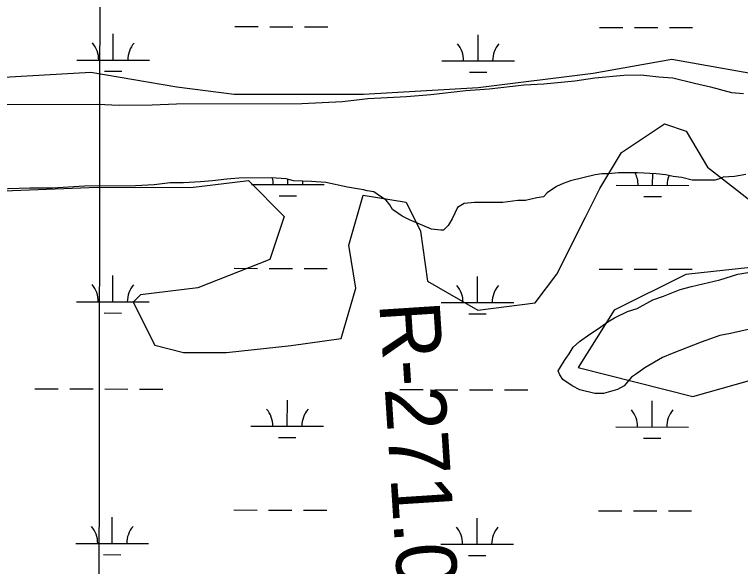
# Model space of a CAD drawing. Extents: x 3219052 to 3256913, y 800770 to 826146.
# Drawn here: x 3228359 to 3229358, y 818838 to 819598 of the extents above; entities that cross this region are included whole.
import ezdxf

# ---------------------------------------------------------------- set-up
doc = ezdxf.new("R2010")
doc.units = 0
for name, color, linetype in [('V-GRID-MAJR', 7, 'Continuous'), ('V-RIVR-RANG-IDEN', 7, 'Continuous'), ('V-SITE-VEGE', 7, 'Continuous'), ('V-TOPO-SHOR', 7, 'Continuous'), ('V-WETL-SWMP', 7, 'Continuous')]:
    doc.layers.add(name, color=color, linetype=linetype)

msp = doc.modelspace()

# ---------------------------------------------------------------- linework, layer by layer
at = {"layer": 'V-GRID-MAJR'}
msp.add_spline([(3228457.14, 806177.393), (3228465.955, 812237.661), (3228474.772, 818299.872), (3228483.589, 824362.121), (3228483.592, 824364.024)], degree=3, dxfattribs=at)
at = {"layer": 'V-SITE-VEGE'}
for p, q in [((3229157.156, 819510.517), (3229197.319, 819514.5430000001)), ((3229197.319, 819514.5429999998), (3229220.648, 819514.6229999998)), ((3229220.648, 819514.623), (3229245.281, 819512.116)), ((3229087.196, 819502.501), (3229129.95, 819506.536)), ((3229129.95, 819506.536), (3229157.156, 819510.517)), ((3229245.281, 819512.1159999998), (3229264.725, 819510.886)), ((3229264.725, 819510.886), (3229294.56, 819503.214)), ((3229294.56, 819503.214), (3229316.611, 819498.104)), ((3228931.724, 819487.71), (3228979.66, 819493.06)), ((3228979.66, 819493.06), (3229012.051, 819495.763)), ((3229012.051, 819495.763), (3229059.984, 819501.111)), ((3229059.984, 819501.111), (3229087.196, 819502.501)), ((3229316.611, 819498.104), (3229345.15, 819490.4280000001)), ((3228844.9080000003, 819482.228), (3228898.039, 819485.003)), ((3228898.039, 819485.0029999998), (3228931.724, 819487.71)), ((3229345.15, 819490.4279999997), (3229362.003, 819489.1869999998)), ((3228259.128, 819473.737), (3228472.972, 819474.47)), ((3228472.972, 819474.4699999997), (3228502.785, 819473.2779999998)), ((3228502.785, 819473.2779999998), (3228548.146, 819473.4339999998)), ((3228548.146, 819473.4339999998), (3228581.838, 819474.8449999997)), ((3228581.838, 819474.845), (3228754.21, 819475.437)), ((3228754.21, 819475.4369999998), (3228809.93, 819478.22)), ((3228809.93, 819478.22), (3228844.9080000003, 819482.228)), ((3228711.792, 819372.9059999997), (3228667.727, 819372.7519999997)), ((3228732.532, 819371.6829999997), (3228711.792, 819372.9059999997)), ((3229157.615, 819377.0259999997), (3229123.943, 819369.1349999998)), ((3229166.681, 819378.353), (3229157.615, 819377.0260000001)), ((3229175.754, 819378.384), (3229166.681, 819378.353)), ((3229190.006, 819379.73), (3229175.754, 819378.384)), ((3229215.923, 819379.8200000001), (3229190.006, 819379.73)), ((3229241.8510000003, 819378.611), (3229215.923, 819379.8200000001)), ((3229254.815, 819377.36), (3229241.8510000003, 819378.611)), ((3229265.194, 819374.8039999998), (3229254.815, 819377.3599999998)), ((3229276.861, 819373.549), (3229265.194, 819374.8039999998)), ((3229291.134, 819369.7089999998), (3229276.861, 819373.549)), ((3229333.886, 819373.7429999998), (3229327.414, 819371.1299999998)), ((3229349.434, 819375.0929999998), (3229333.886, 819373.7429999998)), ((3229364.977, 819377.7390000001), (3229349.434, 819375.0929999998)), ((3228551.116, 819363.2799999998), (3228525.2, 819361.8960000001)), ((3228573.14, 819365.949), (3228551.116, 819363.2799999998)), ((3228591.2830000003, 819366.01), (3228573.14, 819365.949)), ((3228614.608, 819367.3879999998), (3228591.2830000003, 819366.01)), ((3228631.451, 819368.7399999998), (3228614.608, 819367.3879999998)), ((3228650.882, 819371.398), (3228631.451, 819368.7399999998)), ((3228667.727, 819372.7519999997), (3228650.882, 819371.398)), ((3228742.909, 819369.123), (3228732.532, 819371.6829999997)), ((3228767.538, 819367.9130000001), (3228742.909, 819369.123)), ((3228786.984, 819366.6819999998), (3228767.538, 819367.9129999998)), ((3228816.813, 819360.3039999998), (3228786.984, 819366.6819999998)), ((3229113.589, 819365.211), (3229104.5300000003, 819361.2919999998)), ((3229123.943, 819369.135), (3229113.589, 819365.211)), ((3229322.237, 819369.8149999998), (3229291.134, 819369.7089999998)), ((3229327.414, 819371.13), (3229322.237, 819369.8150000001)), ((3228380.052, 819358.805), (3228332.107, 819357.345)), ((3228411.16, 819358.912), (3228380.052, 819358.805)), ((3228455.214, 819361.654), (3228411.16, 819358.912)), ((3228525.2, 819361.8960000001), (3228455.214, 819361.654)), ((3228838.86, 819356.491), (3228816.813, 819360.304)), ((3228844.0470000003, 819355.2129999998), (3228838.86, 819356.4909999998)), ((3228853.124, 819353.9489999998), (3228844.0470000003, 819355.2129999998)), ((3228862.219, 819347.4999999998), (3228853.124, 819353.9489999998)), ((3229104.5300000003, 819361.2919999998), (3229091.6010000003, 819352.176)), ((3228870.014, 819342.3429999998), (3228862.219, 819347.4999999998)), ((3229077.3680000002, 819345.6489999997), (3229061.828, 819341.7039999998)), ((3229086.434, 819346.974), (3229077.3680000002, 819345.649)), ((3229091.6010000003, 819352.176), (3229086.434, 819346.974)), ((3228875.22, 819335.8799999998), (3228870.014, 819342.3429999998)), ((3228879.13, 819329.414), (3228875.22, 819335.8799999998)), ((3228977.597, 819337.529), (3228968.545, 819332.312)), ((3228991.852, 819338.872), (3228977.597, 819337.529)), ((3229030.733, 819339.005), (3228991.852, 819338.872)), ((3229051.461, 819341.67), (3229030.733, 819339.005)), ((3229061.828, 819341.704), (3229051.461, 819341.67)), ((3228892.12, 819320.3869999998), (3228879.13, 819329.414)), ((3228968.545, 819332.312), (3228960.822, 819316.733)), ((3228902.508, 819315.2359999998), (3228892.12, 819320.3869999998)), ((3228920.677, 819307.523), (3228902.508, 819315.2359999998)), ((3228960.822, 819316.733), (3228955.669, 819307.6439999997)), ((3228932.359, 819302.3809999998), (3228920.677, 819307.523)), ((3228955.669, 819307.6439999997), (3228949.2120000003, 819301.142)), ((3228945.323, 819301.127), (3228932.359, 819302.3809999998)), ((3228949.2120000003, 819301.142), (3228945.323, 819301.127)), ((3229353.786, 819240.3200000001), (3229370.625, 819242.97)), ((3229329.188, 819232.4599999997), (3229353.786, 819240.3200000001)), ((3229274.799, 819219.314), (3229290.3370000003, 819223.2540000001)), ((3229290.3370000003, 819223.2540000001), (3229329.188, 819232.46)), ((3229251.499, 819210.1589999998), (3229274.799, 819219.314)), ((3229215.272, 819193.188), (3229237.2630000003, 819204.9269999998)), ((3229237.2630000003, 819204.9269999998), (3229251.499, 819210.1589999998)), ((3229202.324, 819189.2549999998), (3229215.272, 819193.188)), ((3229184.2120000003, 819180.121), (3229202.324, 819189.255)), ((3229162.227, 819165.789), (3229175.156, 819174.905)), ((3229175.156, 819174.905), (3229184.2120000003, 819180.121)), ((3229150.59, 819157.9719999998), (3229162.227, 819165.789)), ((3229372.188, 819165.2139999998), (3229343.698, 819158.636)), ((3229136.369, 819147.5539999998), (3229150.59, 819157.9719999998)), ((3229329.45, 819155.9940000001), (3229303.559, 819146.835)), ((3229343.698, 819158.636), (3229329.45, 819155.9940000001)), ((3229127.325, 819139.747), (3229136.369, 819147.5539999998)), ((3229303.559, 819146.835), (3229263.437, 819131.143)), ((3229122.1720000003, 819130.6579999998), (3229127.325, 819139.747)), ((3229115.723, 819121.5650000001), (3229122.1720000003, 819130.6579999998)), ((3229250.4930000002, 819125.915), (3229225.919, 819111.5749999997)), ((3229263.437, 819131.143), (3229250.4930000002, 819125.915)), ((3229109.278, 819111.1730000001), (3229115.723, 819121.5650000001)), ((3229106.697, 819107.2760000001), (3229109.278, 819111.1730000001)), ((3229109.308, 819102.1009999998), (3229106.697, 819107.2760000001)), ((3229225.919, 819111.5749999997), (3229212.99, 819102.4569999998)), ((3229113.218, 819095.635), (3229109.308, 819102.1009999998)), ((3229126.211, 819086.6079999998), (3229113.218, 819095.635)), ((3229207.819, 819098.552), (3229197.491, 819086.851)), ((3229212.99, 819102.4569999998), (3229207.819, 819098.552)), ((3229136.596, 819081.4589999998), (3229126.211, 819086.6079999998)), ((3229197.491, 819086.851), (3229188.437, 819081.635)), ((3229157.35, 819076.345), (3229136.596, 819081.459)), ((3229169.014, 819076.386), (3229157.35, 819076.345)), ((3229188.437, 819081.635), (3229169.014, 819076.386))]:
    msp.add_line(p, q, dxfattribs=at)
at = {"layer": 'V-TOPO-SHOR'}
for points in [[(3229431.101306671, 819506.0393770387), (3229263.365659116, 819536.0024266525), (3229154.749294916, 819516.4890830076), (3228996.780662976, 819497.0791772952), (3228838.8327186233, 819487.5397251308), (3228790.3889561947, 819487.6412589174)], [(3228790.3889561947, 819487.6412589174), (3228661.164554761, 819487.9121016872), (3228582.221613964, 819497.9480559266), (3228463.8175465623, 819517.9372140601), (3228295.9991486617, 819508.418449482), (3228138.0512043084, 819498.8789973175), (3227970.232806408, 819489.3602327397), (3227832.025769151, 819479.7794054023), (3227703.709873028, 819480.0483440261)], [(3228226.574972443, 819350.6360058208), (3228473.3569987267, 819359.989269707), (3228601.67289485, 819359.720331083), (3228680.6572108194, 819369.4252839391), (3228729.9060406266, 819319.9695782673), (3228710.041008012, 819260.7882321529), (3228611.253722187, 819221.5132938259), (3228532.2694062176, 819211.8083409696), (3228522.378265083, 819201.9585750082), (3228551.865500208, 819142.6737909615), (3228591.326626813, 819132.7205870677), (3228650.5493481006, 819132.5964615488), (3228739.404117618, 819142.2807268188), (3228808.51798004, 819152.0063672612), (3228828.4037002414, 819221.0581669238), (3228818.6573722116, 819280.3015757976), (3228838.543092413, 819349.3533754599), (3228897.7451261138, 819339.3587963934), (3228917.4032828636, 819299.8356070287), (3228927.1289233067, 819230.721744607), (3228996.139347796, 819191.0951173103), (3229075.123663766, 819200.8000701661), (3229104.8177747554, 819240.2198215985), (3229144.4650896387, 819319.100699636), (3229164.2887470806, 819358.5411386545), (3229194.0035456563, 819407.8313436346), (3229253.3090172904, 819447.1890323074), (3229282.899690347, 819437.2565160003), (3229312.407613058, 819387.8421855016), (3229401.096881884, 819318.5628223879)], [(3229371.340708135, 819249.5317103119), (3229282.485938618, 819239.8474450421), (3229183.677965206, 819190.7020531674), (3229134.160196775, 819111.8418627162), (3229292.0047031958, 819072.0290471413), (3229430.273803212, 819111.2212351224)]]:
    msp.add_lwpolyline(points, dxfattribs=at)
at = {"layer": 'V-WETL-SWMP'}
for p, q in [((3228661.935138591, 819581.1993197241), (3228693.9350682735, 819581.1322507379)), ((3228709.9350331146, 819581.0987162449), (3228741.934962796, 819581.0316472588)), ((3228757.934927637, 819580.9981127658), (3228789.93485732, 819580.9310437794)), ((3229163.842035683, 819580.1473678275), (3229195.8419653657, 819580.0802988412)), ((3229211.8419302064, 819580.0467643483), (3229243.8418598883, 819579.9796953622)), ((3229259.841824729, 819579.9461608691), (3229291.841754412, 819579.8790918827)), ((3228494.7741956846, 819535.1196136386), (3228494.8496460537, 819571.1195023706)), ((3228996.6810927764, 819534.067661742), (3228996.7565431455, 819570.067550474)), ((3228444.7743055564, 819535.2244089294), (3228544.7740858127, 819535.0148183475)), ((3228946.681202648, 819534.1724570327), (3229046.6809829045, 819533.9628664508)), ((3228482.741881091, 819519.7138122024), (3228506.7418283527, 819519.663510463)), ((3228984.648778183, 819518.6618603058), (3229008.6487254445, 819518.6115585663)), ((3229157.155977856, 819510.5163820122), (3229197.318977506, 819514.5423722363)), ((3229197.318977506, 819514.5423722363), (3229220.646977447, 819514.6223705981)), ((3229220.646977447, 819514.6223705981), (3229245.280977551, 819512.1153735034)), ((3229087.1969785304, 819502.5004008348), (3229129.9529781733, 819506.535390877)), ((3229129.9529781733, 819506.5353908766), (3229157.155977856, 819510.5163820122)), ((3229245.280977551, 819512.1153735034), (3229264.7249775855, 819510.8853744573)), ((3229264.7249775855, 819510.8853744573), (3229294.5609780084, 819503.2123862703)), ((3229294.5609780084, 819503.2123862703), (3229316.6109782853, 819498.1033939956)), ((3228931.7239798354, 819487.7104372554), (3228979.6589793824, 819493.0584246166)), ((3228979.6589793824, 819493.0584246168), (3229012.0499791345, 819495.7624177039)), ((3229012.0499791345, 819495.7624177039), (3229059.984978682, 819501.1104050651)), ((3229059.984978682, 819501.1104050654), (3229087.1969785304, 819502.5004008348)), ((3229316.6109782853, 819498.1033939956), (3229345.149978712, 819490.4254059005)), ((3228844.907980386, 819482.2274526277), (3228898.0359800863, 819485.0024442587)), ((3228898.0359800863, 819485.0024442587), (3228931.7239798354, 819487.7104372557)), ((3229345.149978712, 819490.4254059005), (3229362.002978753, 819489.1874070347)), ((3228259.128982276, 819473.7365053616), (3228472.9719817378, 819474.4704903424)), ((3228472.9719817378, 819474.4704903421), (3228502.7849817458, 819473.2774905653)), ((3228502.7849817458, 819473.2774905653), (3228548.1459816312, 819473.4324873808)), ((3228548.1459816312, 819473.4324873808), (3228581.8379814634, 819474.8444826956)), ((3228581.8379814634, 819474.8444826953), (3228754.2089810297, 819475.4364705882)), ((3228754.2089810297, 819475.4364705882), (3228809.9289807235, 819478.2194620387)), ((3228809.9289807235, 819478.2194620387), (3228844.907980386, 819482.2274526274)), ((3228711.7909876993, 819372.9036567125), (3228667.7269878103, 819372.7526598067)), ((3228732.53198773, 819371.6796575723), (3228711.7909876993, 819372.9036567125)), ((3229157.613986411, 819377.0266207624), (3229123.9439869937, 819369.1346370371)), ((3229166.6819863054, 819378.3536178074), (3229157.613986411, 819377.0266207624)), ((3229175.7539862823, 819378.3846171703), (3229166.6819863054, 819378.3536178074)), ((3229190.004986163, 819379.7296138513), (3229175.7539862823, 819378.3846171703)), ((3229215.925986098, 819379.8186120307), (3229190.004986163, 819379.7296138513)), ((3229241.850986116, 819378.6116125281), (3229215.925986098, 819379.8186120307)), ((3229236.794567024, 819362.7511830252), (3229236.8282982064, 819378.8454556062)), ((3229254.814986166, 819377.3606139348), (3229241.850986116, 819378.6116125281)), ((3229265.1929863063, 819374.8036178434), (3229254.814986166, 819377.3606139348)), ((3229276.8609863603, 819373.5476193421), (3229265.1929863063, 819374.8036178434)), ((3229291.130986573, 819369.7086252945), (3229276.8609863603, 819373.5476193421)), ((3229333.885986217, 819373.7436153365), (3229327.4149863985, 819371.1296204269)), ((3229349.4339860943, 819375.0926119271), (3229333.885986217, 819373.7436153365)), ((3229364.976985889, 819377.7386061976), (3229349.4339860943, 819375.0926119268)), ((3228551.115988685, 819363.2806842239), (3228525.1999888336, 819361.8956883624)), ((3228573.1389884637, 819365.947678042), (3228551.115988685, 819363.2806842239)), ((3228591.2839884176, 819366.0096767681), (3228573.1389884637, 819365.947678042)), ((3228614.607988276, 819367.3866728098), (3228591.2839884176, 819366.0096767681)), ((3228631.4509881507, 819368.7396693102), (3228614.607988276, 819367.3866728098)), ((3228650.8829879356, 819371.3986633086), (3228631.4509881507, 819368.7396693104)), ((3228667.7269878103, 819372.7526598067), (3228650.8829879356, 819371.3986633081)), ((3228684.8877798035, 819363.9079302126), (3228784.8875600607, 819363.6983396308)), ((3228742.9089878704, 819369.1226614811), (3228732.53198773, 819371.6796575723)), ((3228734.887669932, 819363.8031349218), (3228734.9029534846, 819371.0954280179)), ((3228767.537987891, 819367.9116620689), (3228742.9089878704, 819369.1226614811)), ((3228786.9829879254, 819366.6816630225), (3228767.537987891, 819367.9116620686)), ((3228816.8139882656, 819360.3046725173), (3228786.9829879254, 819366.6816630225)), ((3229113.5889872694, 819365.2106447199), (3229104.5299875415, 819361.2916523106)), ((3229123.9439869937, 819369.1346370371), (3229113.5889872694, 819365.2106447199)), ((3229186.7946768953, 819362.8559783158), (3229286.7944571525, 819362.6463877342)), ((3229322.234986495, 819369.8156231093), (3229291.130986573, 819369.7086252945)), ((3229327.4149863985, 819371.1296204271), (3229322.234986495, 819369.8156231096)), ((3228380.0549893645, 819358.8047031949), (3228332.105989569, 819357.3447088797)), ((3228411.1589892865, 819358.9117010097), (3228380.0549893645, 819358.8047031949)), ((3228455.2149890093, 819361.6546932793), (3228411.1589892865, 819358.9117010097)), ((3228525.1999888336, 819361.8956883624), (3228455.2149890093, 819361.6546932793)), ((3228838.858988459, 819356.4916779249), (3228816.8139882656, 819360.3046725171)), ((3228844.0479885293, 819355.2136798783), (3228838.858988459, 819356.4916779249)), ((3228853.1249885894, 819353.9486815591), (3228844.0479885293, 819355.2136798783)), ((3228862.2189889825, 819347.4996925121), (3228853.1249885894, 819353.9486815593)), ((3229104.5299875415, 819361.2916523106), (3229091.600988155, 819352.1756694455)), ((3228722.8553553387, 819348.3973334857), (3228746.8553026, 819348.3470317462)), ((3228870.0129892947, 819342.342701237), (3228862.2189889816, 819347.4996925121)), ((3229077.3669886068, 819345.6466820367), (3229061.827988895, 819341.704690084)), ((3229086.4349885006, 819346.9736790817), (3229077.3669886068, 819345.6466820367)), ((3229091.600988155, 819352.1756694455), (3229086.4349885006, 819346.9736790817)), ((3229224.7622524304, 819347.3453815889), (3229248.762199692, 819347.2950798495)), ((3228875.2189896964, 819335.879712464), (3228870.0129892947, 819342.342701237)), ((3228879.1289901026, 819329.4137237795), (3228875.2189896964, 819335.879712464)), ((3228977.599989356, 819337.527702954), (3228968.545989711, 819332.3127128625)), ((3228991.851989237, 819338.8726996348), (3228977.599989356, 819337.527702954)), ((3229030.73298914, 819339.0056969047), (3228991.851989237, 819338.8726996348)), ((3229051.4599889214, 819341.6686908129), (3229030.73298914, 819339.0056969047)), ((3229061.827988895, 819341.7046900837), (3229051.4599889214, 819341.6686908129)), ((3228892.120990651, 819320.3857390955), (3228879.1289901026, 819329.4137237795)), ((3228968.545989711, 819332.3127128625), (3228960.8229907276, 819316.7337412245)), ((3228902.5069909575, 819315.23674764), (3228892.120990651, 819320.3857390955)), ((3228920.67799141, 819307.5237602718), (3228902.5069909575, 819315.23674764)), ((3228960.8229907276, 819316.7337412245), (3228955.669991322, 819307.6437578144)), ((3228932.3599917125, 819302.3797687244), (3228920.67799141, 819307.5237602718)), ((3228955.669991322, 819307.6437578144), (3228949.2119917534, 819301.1407698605)), ((3228945.3239917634, 819301.1277701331), (3228932.3599917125, 819302.3797687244)), ((3228949.2119917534, 819301.1407698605), (3228945.3239917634, 819301.1277701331)), ((3228661.2379038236, 819248.5253479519), (3228693.2378335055, 819248.4582789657)), ((3228709.2377983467, 819248.4247444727), (3228741.237728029, 819248.3576754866)), ((3228757.23769287, 819248.3241409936), (3228789.237622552, 819248.2570720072)), ((3229163.1448009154, 819247.4733960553), (3229195.1447305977, 819247.406327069)), ((3229211.1446954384, 819247.3727925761), (3229243.144625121, 819247.30572359)), ((3229259.144589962, 819247.2721890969), (3229291.144519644, 819247.2051201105)), ((3229353.7850133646, 819240.3203729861), (3229370.6240131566, 819242.9703671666)), ((3228494.076960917, 819202.4456418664), (3228494.1524112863, 819238.4455305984)), ((3228995.983858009, 819201.3936899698), (3228996.0593083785, 819237.3935787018)), ((3229329.1870139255, 819232.460388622), (3229353.7850133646, 819240.3203729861)), ((3229274.7990148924, 819219.3134156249), (3229290.337014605, 819223.2544075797)), ((3229290.337014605, 819223.2544075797), (3229329.1870139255, 819232.4603886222)), ((3229251.501015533, 819210.1604334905), (3229274.7990148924, 819219.3134156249)), ((3229215.271016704, 819193.1884661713), (3229237.263015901, 819204.9274437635)), ((3229237.263015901, 819204.9274437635), (3229251.501015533, 819210.1604334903)), ((3228444.0770707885, 819202.5504371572), (3228544.0768510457, 819202.3408465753)), ((3228945.9839678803, 819201.4984852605), (3229045.9837481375, 819201.2888946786)), ((3229202.324016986, 819189.2554740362), (3229215.271016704, 819193.1884661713)), ((3228482.044646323, 819187.0398404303), (3228506.044593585, 819186.9895386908)), ((3228983.951543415, 819185.9878885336), (3229007.951490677, 819185.9375867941)), ((3229184.211017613, 819180.1214915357), (3229202.324016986, 819189.2554740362)), ((3229162.2270185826, 819165.7895185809), (3229175.1560179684, 819174.905501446)), ((3229175.1560179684, 819174.905501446), (3229184.211017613, 819180.1214915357)), ((3229150.5900191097, 819157.9735333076), (3229162.2270185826, 819165.7895185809)), ((3229372.187018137, 819165.2135061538), (3229343.697018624, 819158.6355197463)), ((3229136.36901981, 819147.5555528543), (3229150.5900191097, 819157.9735333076)), ((3229329.449018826, 819155.9945253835), (3229303.560019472, 819146.8335434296)), ((3229343.697018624, 819158.6355197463), (3229329.449018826, 819155.9945253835)), ((3229127.3240203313, 819139.7485673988), (3229136.36901981, 819147.5555528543)), ((3229303.560019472, 819146.8335434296), (3229263.4370205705, 819131.1435740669)), ((3229122.1710209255, 819130.6585839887), (3229127.3240203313, 819139.7485673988)), ((3229115.7220215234, 819121.564600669), (3229122.1710209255, 819130.6585839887)), ((3229250.494020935, 819125.9155842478), (3229225.9190219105, 819111.5746114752)), ((3229263.4370205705, 819131.1435740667), (3229250.494020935, 819125.9155842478)), ((3229109.2770222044, 819111.1736196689), (3229115.7220215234, 819121.564600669)), ((3229106.69802246, 819107.2766268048), (3229109.2770222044, 819111.1736196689)), ((3229109.308022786, 819102.1016358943), (3229106.69802246, 819107.2766268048)), ((3229225.9190219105, 819111.5746114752), (3229212.9900225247, 819102.4576286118)), ((3229113.2190231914, 819095.6356472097), (3229109.308022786, 819102.1016358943)), ((3229126.21002374, 819086.6076625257), (3229113.2190231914, 819095.6356472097)), ((3229207.8190227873, 819098.5516359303), (3229197.4910235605, 819086.8526575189)), ((3229212.9900225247, 819102.457628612), (3229207.8190227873, 819098.5516359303)), ((3229136.596024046, 819081.4586710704), (3229126.21002374, 819086.6076625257)), ((3229197.4910235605, 819086.8526575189), (3229188.4370239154, 819081.6366674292)), ((3228386.981545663, 819082.5989479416), (3228418.981475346, 819082.5318789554)), ((3228434.9814401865, 819082.4983444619), (3228466.9813698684, 819082.4312754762)), ((3228482.9813347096, 819082.397740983), (3228514.981264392, 819082.3306719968)), ((3228530.9812292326, 819082.2971375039), (3228562.9811589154, 819082.2300685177)), ((3228888.8884427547, 819081.5469960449), (3228920.8883724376, 819081.4799270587)), ((3228936.8883372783, 819081.4463925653), (3228968.88826696, 819081.3793235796)), ((3228984.888231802, 819081.3457890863), (3229016.8881614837, 819081.2787201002)), ((3229032.888126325, 819081.2451856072), (3229064.8880560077, 819081.178116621)), ((3229157.3500243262, 819076.3456788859), (3229136.596024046, 819081.4586710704)), ((3229169.014024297, 819076.3866780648), (3229157.3500243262, 819076.3456788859)), ((3229188.4370239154, 819081.6366674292), (3229169.014024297, 819076.3866780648)), ((3228734.1904351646, 819031.1291631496), (3228734.2658855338, 819067.1290518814)), ((3229236.0973322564, 819030.077211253), (3229236.1727826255, 819066.0770999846)), ((3228684.1905450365, 819031.2339584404), (3228784.1903252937, 819031.0243678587)), ((3229186.097442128, 819030.1820065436), (3229286.0972223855, 819029.972415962)), ((3228722.158120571, 819015.7233617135), (3228746.158067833, 819015.673059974)), ((3229224.065017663, 819014.6714098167), (3229248.064964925, 819014.6211080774)), ((3228660.540669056, 818915.8513761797), (3228692.540598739, 818915.7843071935)), ((3228708.5405635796, 818915.7507727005), (3228740.5404932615, 818915.6837037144)), ((3228756.5404581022, 818915.6501692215), (3228788.540387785, 818915.583100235)), ((3229162.447566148, 818914.7994242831), (3229194.4474958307, 818914.7323552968)), ((3229210.4474606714, 818914.6988208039), (3229242.4473903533, 818914.6317518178)), ((3229258.447355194, 818914.5982173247), (3229290.447284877, 818914.5311483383)), ((3228493.3797261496, 818869.7716700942), (3228493.4551765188, 818905.7715588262)), ((3228995.2866232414, 818868.7197181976), (3228995.362073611, 818904.7196069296)), ((3228443.3798360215, 818869.876465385), (3228543.3796162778, 818869.6668748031)), ((3228945.286733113, 818868.8245134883), (3229045.2865133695, 818868.6149229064)), ((3228481.347411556, 818854.3658686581), (3228505.3473588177, 818854.3155669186)), ((3228983.2543086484, 818853.3139167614), (3229007.2542559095, 818853.263615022))]:
    msp.add_line(p, q, dxfattribs=at)
for centre, radius, start, end in [((3228439.5323760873, 819535.7101993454), 35.24628790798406, 359.1080939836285, 40.65175231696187), ((3228550.0180055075, 819535.4786313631), 35.246287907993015, 139.10808960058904, 180.65174793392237), ((3228941.439273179, 819534.6582474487), 35.24628790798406, 359.1080939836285, 40.65175231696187), ((3229051.9249025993, 819534.4266794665), 35.246287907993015, 139.10808960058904, 180.65174793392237), ((3229181.552747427, 819363.3417687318), 35.24628790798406, 359.1080939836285, 27.850439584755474), ((3229292.038376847, 819363.1102007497), 35.246287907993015, 158.11566111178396, 180.65174793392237), ((3228679.6458503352, 819364.3937206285), 35.24628790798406, 359.1080939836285, 13.76527917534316), ((3228790.131479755, 819364.1621526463), 35.246287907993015, 172.89696354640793, 180.65174793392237), ((3228438.83514132, 819203.0362275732), 35.24628790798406, 359.1080939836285, 40.65175231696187), ((3228549.3207707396, 819202.8046595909), 35.246287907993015, 139.10808960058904, 180.65174793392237), ((3228940.7420384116, 819201.9842756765), 35.24628790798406, 359.1080939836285, 40.65175231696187), ((3229051.2276678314, 819201.7527076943), 35.246287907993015, 139.10808960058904, 180.65174793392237), ((3228678.948615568, 819031.7197488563), 35.24628790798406, 359.1080939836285, 40.65175231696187), ((3228789.4342449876, 819031.4881808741), 35.246287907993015, 139.10808960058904, 180.65174793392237), ((3229180.85551266, 819030.6677969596), 35.24628790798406, 359.1080939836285, 40.65175231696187), ((3229291.3411420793, 819030.4362289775), 35.246287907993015, 139.10808960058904, 180.65174793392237), ((3228438.1379065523, 818870.362255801), 35.24628790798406, 359.1080939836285, 40.65175231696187), ((3228548.6235359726, 818870.1306878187), 35.246287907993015, 139.10808960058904, 180.65174793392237), ((3228940.044803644, 818869.3103039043), 35.24628790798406, 359.1080939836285, 40.65175231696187), ((3229050.5304330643, 818869.0787359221), 35.246287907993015, 139.10808960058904, 180.65174793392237)]:
    msp.add_arc(centre, radius, start, end, dxfattribs=at)

# ---------------------------------------------------------------- texts
at = {"layer": 'V-RIVR-RANG-IDEN'}
msp.add_text('R-271.05', height=82.99999800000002, rotation=273.71487206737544, dxfattribs=at).set_placement((3228860.6125596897, 819200.5974758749))

doc.saveas('drawing.dxf')
